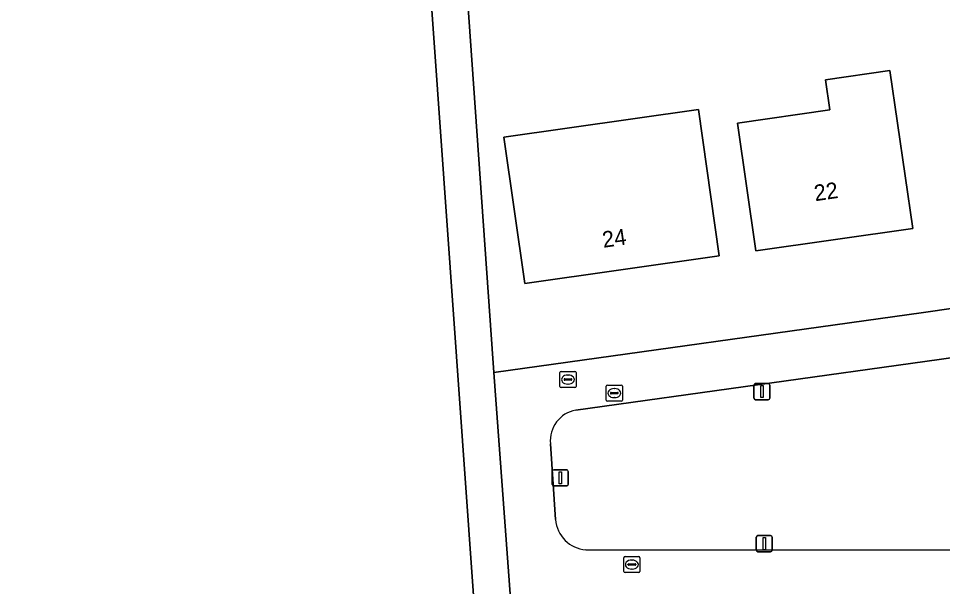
# Model space of a CAD drawing. Extents: x 162661 to 163484, y 380247 to 381230.
# Drawn here: x 162936.2 to 162993.5, y 380630.3 to 380665.5 of the extents above; entities that cross this region are included whole.
import ezdxf

# ---------------------------------------------------------------- set-up
doc = ezdxf.new("R2010")
doc.units = 0
for name, color, linetype in [('IMGEO_Brandkraan', 7, 'Continuous'), ('IMGEO_Erf', 7, 'Continuous'), ('IMGEO_Groenvoorziening', 7, 'Continuous'), ('IMGEO_Lichtmast', 7, 'Continuous'), ('IMGEO_Pand', 7, 'Continuous'), ('IMGEO_Pand_nummerreeks', 7, 'Continuous'), ('IMGEO_Rijbaan_lokaal_open', 7, 'Continuous'), ('IMGEO_Rioolput', 7, 'Continuous'), ('IMGEO_Voetpad_open', 7, 'Continuous')]:
    doc.layers.add(name, color=color, linetype=linetype)

msp = doc.modelspace()

# ---------------------------------------------------------------- linework, layer by layer
at = {"layer": 'IMGEO_Brandkraan'}
for p, q in [((162969.753, 380642.72), (162969.753, 380643.572)), ((162969.828, 380643.646), (162970.68, 380643.646)), ((162970.241, 380643.426), (162970.266, 380643.426)), ((162970.754, 380643.572), (162970.754, 380642.72)), ((162970.012, 380643.14), (162970.012, 380643.152)), ((162970.45, 380643.103), (162970.052, 380643.103)), ((162970.055, 380643.189), (162970.453, 380643.189)), ((162970.264, 380642.866), (162970.239, 380642.866)), ((162970.496, 380643.152), (162970.496, 380643.14)), ((162970.68, 380642.646), (162969.828, 380642.646))]:
    msp.add_line(p, q, dxfattribs=at)
for points in [[(162969.753, 380642.72), (162969.753, 380643.572)], [(162969.828, 380643.646), (162970.68, 380643.646)], [(162970.754, 380643.572), (162970.754, 380642.72)], [(162970.68, 380642.646), (162969.828, 380642.646)]]:
    msp.add_lwpolyline(points, dxfattribs=at)
for centre, radius, start, end in [((162969.83, 380643.57), 0.0765, 91.552, 178.448), ((162969.83, 380643.57), 0.0765, 91.552, 178.448), ((162970.678, 380643.57), 0.0765, 1.552, 88.448), ((162970.678, 380643.57), 0.0765, 1.552, 88.448), ((162970.052, 380643.149), 0.0403, 85.8775, 175.7526), ((162970.049, 380643.139), 0.0366, 178.938, 274.7102), ((162970.453, 380643.146), 0.043, 264.8664, 352.4533), ((162970.457, 380643.151), 0.0386, 1.7309, 96.639), ((162969.83, 380642.722), 0.0765, 181.552, 268.448), ((162969.83, 380642.722), 0.0765, 181.552, 268.448), ((162970.678, 380642.722), 0.0765, 271.552, 358.448), ((162970.678, 380642.722), 0.0765, 271.552, 358.448)]:
    msp.add_arc(centre, radius, start, end, dxfattribs=at)
for centre, major_axis, ratio, start_param, end_param in [((162970.24, 380643.146), (-0.387, 0.002), 0.722429, 4.712389, 7.853982), ((162970.265, 380643.146), (-0.39, 0.002), 0.717154, 1.570796, 4.712389)]:
    msp.add_ellipse(centre, major_axis=major_axis, ratio=ratio, start_param=start_param, end_param=end_param, dxfattribs=at)
at = {"layer": 'IMGEO_Erf'}
msp.add_lwpolyline([(163000, 380694.393), (162962.071, 380694.445), (162962.409, 380689.802), (162962.491, 380688.633), (162963.778, 380670.344), (162965.454, 380670.466), (162968.024, 380670.653), (162968.22, 380667.959), (162965.65, 380667.772), (162963.967, 380667.65), (162965.66, 380643.591), (162992.266, 380647.305), (163000, 380648.404)], dxfattribs=at)
for points in [[(162986.465, 380659.85), (162986.198, 380661.711), (162990.197, 380662.286), (162991.607, 380652.505), (162981.89, 380651.109), (162980.753, 380659.029)], [(162979.623, 380650.808), (162967.585, 380649.089), (162966.286, 380658.154), (162978.328, 380659.874)]]:
    msp.add_lwpolyline(points, close=True, dxfattribs=at)
at = {"layer": 'IMGEO_Groenvoorziening'}
msp.add_lwpolyline([(162965.305, 380617.196), (162958.775, 380616.334), (162958.723, 380616.73), (162965.276, 380617.596), (162960.246, 380688.108), (162960.008, 380688.147), (162954.674, 380687.332), (162953.589, 380687.308), (162953.392, 380687.138), (162952.628, 380686.48), (162952.001, 380686.244), (162913.666, 380677.887), (162935.364, 380613.543), (162943.88, 380614.582), (162943.646, 380616.461), (162957.527, 380618.146), (162957.849, 380615.707), (162965.351, 380616.545)], close=True, dxfattribs=at)
for points in [[(162971.366, 380632.606), (162995.104, 380632.58), (163000, 380632.57), (163018.199, 380632.533), (163019.234, 380632.502), (163019.199, 380632.945), (163018.17, 380647.491), (163018.149, 380647.927), (163000, 380645.353), (162993.249, 380644.396), (162970.741, 380641.258)], [(162969.163, 380639.164), (162969.487, 380634.48)]]:
    msp.add_lwpolyline(points, dxfattribs=at)
for centre, radius, start, end in [((162971.106, 380639.342), 1.951, 100.774, 185.224), ((162971.488, 380634.608), 2.006, 183.6534, 266.4993)]:
    msp.add_arc(centre, radius, start, end, dxfattribs=at)
at = {"layer": 'IMGEO_Lichtmast'}
for p, q in [((162981.868, 380642.898), (162982.658, 380642.898)), ((162982.658, 380642.898), (162981.868, 380642.898)), ((162981.768, 380641.998), (162981.768, 380642.798)), ((162981.768, 380642.798), (162981.768, 380641.998)), ((162982.758, 380642.798), (162982.758, 380641.998)), ((162982.758, 380641.998), (162982.758, 380642.798)), ((162982.658, 380641.898), (162981.868, 380641.898)), ((162981.868, 380641.898), (162982.658, 380641.898)), ((162969.285, 380636.654), (162969.285, 380637.454)), ((162969.285, 380637.454), (162969.285, 380636.654)), ((162969.385, 380637.554), (162970.175, 380637.554)), ((162970.175, 380637.554), (162969.385, 380637.554)), ((162970.275, 380637.454), (162970.275, 380636.654)), ((162970.275, 380636.654), (162970.275, 380637.454)), ((162970.175, 380636.554), (162969.385, 380636.554)), ((162969.385, 380636.554), (162970.175, 380636.554)), ((162981.915, 380632.581), (162981.915, 380633.381)), ((162981.915, 380633.381), (162981.915, 380632.581)), ((162982.015, 380633.481), (162982.805, 380633.481)), ((162982.805, 380633.481), (162982.015, 380633.481)), ((162982.905, 380633.381), (162982.905, 380632.581)), ((162982.905, 380632.581), (162982.905, 380633.381)), ((162982.805, 380632.481), (162982.015, 380632.481)), ((162982.015, 380632.481), (162982.805, 380632.481))]:
    msp.add_line(p, q, dxfattribs=at)
for points in [[(162982.188, 380642.773), (162982.338, 380642.773), (162982.338, 380642.023), (162982.188, 380642.023), (162982.188, 380642.773)], [(162969.705, 380637.429), (162969.855, 380637.429), (162969.855, 380636.679), (162969.705, 380636.679), (162969.705, 380637.429)], [(162982.335, 380633.356), (162982.485, 380633.356), (162982.485, 380632.606), (162982.335, 380632.606), (162982.335, 380633.356)]]:
    msp.add_lwpolyline(points, dxfattribs=at)
for centre, start, end in [((162981.868, 380642.798), 90, 180), ((162981.868, 380642.798), 90, 180), ((162982.658, 380642.798), 0, 90), ((162982.658, 380642.798), 360, 90), ((162981.868, 380641.998), 180, 270), ((162981.868, 380641.998), 180, 270), ((162982.658, 380641.998), 270, 0), ((162982.658, 380641.998), 270, 0), ((162969.385, 380637.454), 90, 180), ((162969.385, 380637.454), 90, 180), ((162970.175, 380637.454), 0, 90), ((162970.175, 380637.454), 360, 90), ((162969.385, 380636.654), 180, 270), ((162969.385, 380636.654), 180, 270), ((162970.175, 380636.654), 270, 0), ((162970.175, 380636.654), 270, 0), ((162982.015, 380633.381), 90, 180), ((162982.015, 380633.381), 90, 180), ((162982.805, 380633.381), 0, 90), ((162982.805, 380633.381), 360, 90), ((162982.015, 380632.581), 180, 270), ((162982.015, 380632.581), 180, 270), ((162982.805, 380632.581), 270, 0), ((162982.805, 380632.581), 270, 0)]:
    msp.add_arc(centre, 0.1, start, end, dxfattribs=at)
at = {"layer": 'IMGEO_Pand'}
for points in [[(162981.89, 380651.109), (162991.607, 380652.505), (162990.197, 380662.286), (162986.198, 380661.711), (162986.465, 380659.85), (162980.753, 380659.029)], [(162966.286, 380658.154), (162967.585, 380649.089), (162979.623, 380650.808), (162978.328, 380659.874)]]:
    msp.add_lwpolyline(points, close=True, dxfattribs=at)
at = {"layer": 'IMGEO_Rijbaan_lokaal_open'}
for points in [[(162970.741, 380641.258), (162993.249, 380644.396), (163000, 380645.353), (163018.149, 380647.927), (163017.717, 380650.948), (163014.757, 380650.503), (163000, 380648.404), (162992.266, 380647.305), (162965.66, 380643.591), (162966.701, 380629.588), (162995.135, 380629.56), (163000, 380629.551), (163019.499, 380629.512), (163019.234, 380632.502), (163018.199, 380632.533), (163000, 380632.57), (162995.104, 380632.58), (162971.366, 380632.606)], [(162969.487, 380634.48), (162969.163, 380639.164)]]:
    msp.add_lwpolyline(points, dxfattribs=at)
for centre, radius, start, end in [((162971.106, 380639.342), 1.951, 100.774, 185.224), ((162971.488, 380634.608), 2.006, 183.6534, 266.4993)]:
    msp.add_arc(centre, radius, start, end, dxfattribs=at)
at = {"layer": 'IMGEO_Rioolput'}
for p, q in [((162972.7, 380642.804), (162973.552, 380642.804)), ((162972.625, 380641.878), (162972.625, 380642.73)), ((162972.884, 380642.298), (162972.884, 380642.31)), ((162973.322, 380642.261), (162972.924, 380642.261)), ((162972.927, 380642.347), (162973.325, 380642.347)), ((162973.113, 380642.584), (162973.138, 380642.584)), ((162973.368, 380642.31), (162973.368, 380642.298)), ((162973.626, 380642.73), (162973.626, 380641.878)), ((162973.552, 380641.804), (162972.7, 380641.804)), ((162973.136, 380642.024), (162973.111, 380642.024)), ((162973.712, 380631.262), (162973.712, 380632.114)), ((162973.787, 380632.188), (162974.639, 380632.188)), ((162974.2, 380631.968), (162974.225, 380631.968)), ((162974.713, 380632.114), (162974.713, 380631.262)), ((162973.971, 380631.682), (162973.971, 380631.694)), ((162974.409, 380631.645), (162974.011, 380631.645)), ((162974.014, 380631.731), (162974.412, 380631.731)), ((162974.223, 380631.408), (162974.198, 380631.408)), ((162974.455, 380631.694), (162974.455, 380631.682)), ((162974.639, 380631.188), (162973.787, 380631.188))]:
    msp.add_line(p, q, dxfattribs=at)
for points in [[(162972.7, 380642.804), (162973.552, 380642.804)], [(162972.625, 380641.878), (162972.625, 380642.73)], [(162973.626, 380642.73), (162973.626, 380641.878)], [(162973.552, 380641.804), (162972.7, 380641.804)], [(162973.712, 380631.262), (162973.712, 380632.114)], [(162973.787, 380632.188), (162974.639, 380632.188)], [(162974.713, 380632.114), (162974.713, 380631.262)], [(162974.639, 380631.188), (162973.787, 380631.188)]]:
    msp.add_lwpolyline(points, dxfattribs=at)
for centre, radius, start, end in [((162972.702, 380642.728), 0.0765, 91.552, 178.448), ((162972.702, 380642.728), 0.0765, 91.552, 178.448), ((162973.55, 380642.728), 0.0765, 1.552, 88.448), ((162973.55, 380642.728), 0.0765, 1.552, 88.448), ((162972.924, 380642.307), 0.0403, 85.8775, 175.7526), ((162972.921, 380642.297), 0.0366, 178.938, 274.7102), ((162973.325, 380642.304), 0.043, 264.8664, 352.4533), ((162973.329, 380642.309), 0.0386, 1.7309, 96.639), ((162972.702, 380641.88), 0.0765, 181.552, 268.448), ((162972.702, 380641.88), 0.0765, 181.552, 268.448), ((162973.55, 380641.88), 0.0765, 271.552, 358.448), ((162973.55, 380641.88), 0.0765, 271.552, 358.448), ((162973.789, 380632.112), 0.0765, 91.552, 178.448), ((162973.789, 380632.112), 0.0765, 91.552, 178.448), ((162974.637, 380632.112), 0.0765, 1.552, 88.448), ((162974.637, 380632.112), 0.0765, 1.552, 88.448), ((162974.011, 380631.691), 0.0403, 85.8775, 175.7526), ((162974.008, 380631.681), 0.0366, 178.938, 274.7102), ((162974.412, 380631.688), 0.043, 264.8664, 352.4533), ((162974.416, 380631.693), 0.0386, 1.7309, 96.639), ((162973.789, 380631.264), 0.0765, 181.552, 268.448), ((162973.789, 380631.264), 0.0765, 181.552, 268.448), ((162974.637, 380631.264), 0.0765, 271.552, 358.448), ((162974.637, 380631.264), 0.0765, 271.552, 358.448)]:
    msp.add_arc(centre, radius, start, end, dxfattribs=at)
for centre, major_axis, ratio, start_param, end_param in [((162973.112, 380642.304), (-0.387, 0.002), 0.722429, 4.712389, 7.853982), ((162973.137, 380642.304), (-0.39, 0.002), 0.717154, 1.570796, 4.712389), ((162974.199, 380631.688), (-0.387, 0.002), 0.722429, 4.712389, 7.853982), ((162974.224, 380631.688), (-0.39, 0.002), 0.717154, 1.570796, 4.712389)]:
    msp.add_ellipse(centre, major_axis=major_axis, ratio=ratio, start_param=start_param, end_param=end_param, dxfattribs=at)
at = {"layer": 'IMGEO_Voetpad_open'}
msp.add_lwpolyline([(162966.959, 380625.81), (162966.701, 380629.588), (162965.66, 380643.591), (162963.967, 380667.65), (162963.778, 380670.344), (162962.491, 380688.633), (162962.409, 380689.802), (162962.071, 380694.445), (162959.414, 380694.449), (162960.008, 380688.147), (162960.246, 380688.108), (162965.276, 380617.596), (162965.305, 380617.196), (162965.351, 380616.545), (162965.481, 380615.267), (162969.587, 380558.14), (162969.886, 380553.083), (162972.784, 380512.688), (162974.83, 380512.958), (162971.633, 380560.525), (162971.283, 380565.188), (162970.367, 380578.072), (162969.904, 380584.293)], close=True, dxfattribs=at)

# ---------------------------------------------------------------- texts
at = {"layer": 'IMGEO_Pand_nummerreeks'}
for s, rotation, p in [('22', 8.1747, (162985.567, 380654.184)), ('24', 7.9297, (162972.448, 380651.302))]:
    msp.add_text(s, height=1, rotation=rotation, dxfattribs=at).set_placement(p)

doc.saveas('drawing.dxf')
